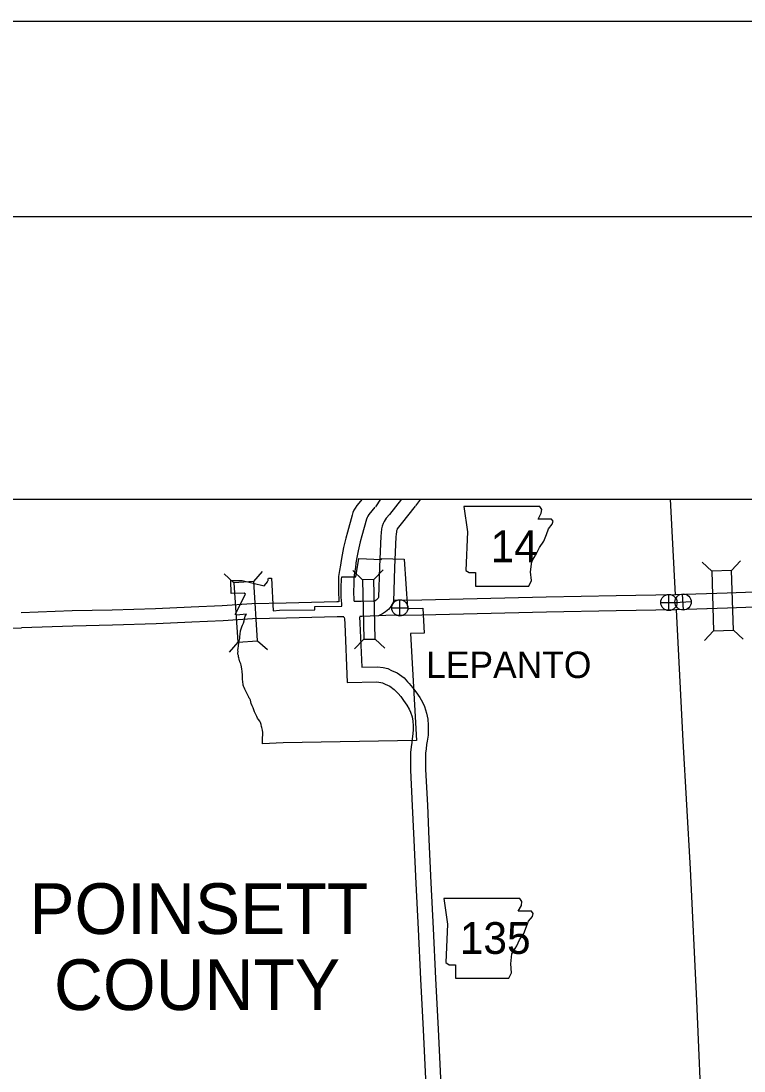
# Model space of a CAD drawing. Extents: x -117616 to 64730, y 54117 to 789866.
# Drawn here: x 61708.6 to 61852.8, y 56041.5 to 56250.9 of the extents above; entities that cross this region are included whole.
import ezdxf

# ---------------------------------------------------------------- set-up
doc = ezdxf.new("R2010")
doc.units = 0
for name, color, linetype in [('10', 7, 'Continuous'), ('2', 7, 'Continuous'), ('20', 7, 'Continuous'), ('26', 7, 'Continuous'), ('Default', 7, 'Continuous'), ('Level 10', 7, 'Continuous'), ('Level 20', 7, 'Continuous'), ('Level 21', 7, 'Continuous'), ('Level 26', 7, 'Continuous'), ('Level 6', 7, 'Continuous'), ('R_Border', 7, 'Continuous'), ('R_No Plot', 7, 'Continuous')]:
    doc.layers.add(name, color=color, linetype=linetype)

msp = doc.modelspace()

# ---------------------------------------------------------------- linework, layer by layer
at = {"layer": '10'}
for points in [[(61894.64, 56138.72), (61871.24, 56137.58), (61849.41, 56136.82), (61839.09, 56136.5)], [(61894.81, 56135.72), (61871.37, 56134.58), (61849.51, 56133.82), (61839.25, 56133.5)], [(61894.81, 56135.72), (61871.37, 56134.58), (61849.51, 56133.82), (61839.35, 56133.5)]]:
    msp.add_lwpolyline(points, dxfattribs=at)
at = {"layer": '2'}
for points in [[(61838.05, 56155.54), (61839.09, 56136.5)], [(61839.25, 56133.5), (61840.62, 56107.34), (61842.03, 56081.82), (61843.35, 56055.55), (61844.48, 56029.1), (61845.71, 56002.55), (61847.12, 55976.46), (61848.14, 55951.87)]]:
    msp.add_lwpolyline(points, dxfattribs=at)
at = {"layer": '20'}
for p, q in [((61846.37, 56141.17), (61844.44, 56142.98)), ((61850.33, 56141.29), (61852.13, 56143.22)), ((61846.74, 56129.29), (61844.94, 56127.37)), ((61850.7, 56129.42), (61852.63, 56127.61))]:
    msp.add_line(p, q, dxfattribs=at)
msp.add_lwpolyline([(61846.37, 56141.17), (61846.74, 56129.29), (61850.7, 56129.42), (61850.33, 56141.29)], close=True, dxfattribs=at)
at = {"layer": '26'}
for p, q in [((61840.75, 56133.41), (61840.55, 56136.66)), ((61839.03, 56134.94), (61842.27, 56135.14))]:
    msp.add_line(p, q, dxfattribs=at)
msp.add_circle((61840.65, 56135.04), 1.62, dxfattribs=at)
at = {"layer": 'Level 10'}
for points in [[(61776.64, 56155.54), (61775.59, 56154.26), (61775.25, 56153.77), (61774.98, 56153.33), (61774.8, 56152.88), (61774.65, 56152.37), (61773.69, 56148.99), (61773.37, 56147.76), (61772.92, 56145.88), (61772.63, 56144.47), (61772.44, 56143.32), (61772.32, 56142.39), (61772.14, 56141.3), (61771.96, 56140.11), (61771.96, 56138.95), (61771.95, 56136.74), (61771.97, 56135.65), (61772, 56135.08)], [(61784.5, 56155.54), (61782.1, 56152.49), (61781.45, 56151.72), (61781.05, 56151.07), (61780.86, 56150.71), (61780.65, 56150.16), (61780.51, 56149.6), (61780.42, 56148.83), (61780.38, 56148.19), (61780.11, 56142.05), (61779.91, 56135.92), (61779.86, 56135.82), (61779.73, 56135.65), (61779.67, 56135.6), (61779.5, 56135.46), (61779.41, 56135.39), (61779.23, 56135.27), (61779.15, 56135.23), (61776.48, 56135.16), (61775.03, 56135.13)], [(61780.29, 56155.54), (61779.28, 56154.03)], [(61788.26, 56155.54), (61787.26, 56154.19)], [(61779.19, 56153.92), (61777.99, 56152.45), (61777.76, 56152.12), (61777.68, 56151.99), (61777.64, 56151.89), (61777.52, 56151.52), (61776.58, 56148.21), (61776.28, 56147.04), (61775.85, 56145.24), (61775.59, 56143.93), (61775.41, 56142.87), (61775.29, 56141.94), (61775.1, 56140.84), (61774.96, 56139.89), (61774.96, 56138.93), (61774.95, 56136.77), (61774.97, 56135.76), (61775, 56135.19)], [(61787.23, 56154.16), (61784.43, 56150.6), (61783.89, 56149.96), (61783.66, 56149.6), (61783.6, 56149.47), (61783.51, 56149.25), (61783.47, 56149.06), (61783.41, 56148.56), (61783.38, 56148.05), (61783.11, 56141.94), (61782.89, 56135.08), (61782.36, 56134.14), (61781.95, 56133.62), (61781.64, 56133.33), (61781.33, 56133.09), (61781.13, 56132.93), (61780.71, 56132.66), (61779.88, 56132.25), (61776.56, 56132.16), (61776.16, 56132.15)], [(61839.12, 56136.48), (61827.28, 56136.28), (61813.36, 56136.01), (61788.52, 56135.42), (61782.97, 56135.37)], [(61771.95, 56135.06), (61771.58, 56135.05), (61761.5, 56134.83), (61754.63, 56134.67), (61748.76, 56134.29), (61742.52, 56134.03), (61735.42, 56133.69), (61726.79, 56133.42), (61718.84, 56133.25), (61708.61, 56132.9)], [(61772.97, 56132.08), (61771.65, 56132.05), (61761.57, 56131.84), (61754.76, 56131.67), (61748.92, 56131.29), (61742.65, 56131.04), (61735.54, 56130.7), (61726.87, 56130.42), (61718.93, 56130.25), (61708.71, 56129.9)], [(61772.99, 56132.04), (61773.06, 56131.94), (61773.14, 56131.65), (61773.2, 56130.67), (61773.68, 56118.97), (61779.58, 56119.09), (61780.34, 56119), (61780.72, 56118.91), (61781.24, 56118.65), (61782.14, 56118.27), (61783.01, 56117.62), (61783.59, 56117.04), (61783.82, 56116.81), (61784.34, 56116.18), (61784.91, 56115.41), (61785.55, 56114.47), (61785.99, 56113.65), (61786.27, 56113.09), (61786.59, 56112.12), (61786.77, 56111.25), (61786.83, 56110.38), (61786.81, 56109.61), (61786.78, 56108.75), (61786.64, 56107.73), (61786.53, 56107.04), (61786.42, 56106.15), (61786.3, 56105.05), (61786.29, 56101.54), (61786.65, 56094.4), (61786.96, 56087.56), (61787.36, 56078.93), (61787.79, 56069.78), (61788.29, 56059.84), (61788.79, 56049.71), (61789.39, 56037.2)], [(61776.12, 56132.08), (61776.2, 56130.83), (61776.56, 56122.03), (61779.73, 56122.09), (61780.86, 56121.96), (61781.74, 56121.75), (61782.48, 56121.38), (61783.64, 56120.9), (61784.99, 56119.89), (61785.72, 56119.15), (61786.05, 56118.82), (61786.7, 56118.02), (61787.35, 56117.15), (61788.12, 56116.03), (61788.65, 56115.04), (61789.05, 56114.23), (61789.49, 56112.89), (61789.74, 56111.65), (61789.83, 56110.46), (61789.81, 56109.53), (61789.78, 56108.49), (61789.61, 56107.3), (61789.51, 56106.63), (61789.4, 56105.79), (61789.29, 56104.87), (61789.29, 56101.62), (61789.65, 56094.55), (61789.95, 56087.7), (61790.36, 56079.07), (61790.79, 56069.92), (61791.29, 56059.99), (61791.78, 56049.86), (61792.39, 56037.32)], [(61839.23, 56133.48), (61827.33, 56133.28), (61813.42, 56133.01), (61788.57, 56132.42), (61781.38, 56132.36), (61779.97, 56132.27)], [(61702.66, 56129.67), (61708.72, 56129.9)]]:
    msp.add_lwpolyline(points, dxfattribs=at)
at = {"layer": 'Level 20'}
for p, q in [((61751.08, 56138.89), (61749.1, 56140.63)), ((61755.04, 56139.14), (61756.78, 56141.13)), ((61776.69, 56139.49), (61774.78, 56141.31)), ((61779, 56139.54), (61780.83, 56141.45)), ((61779, 56139.54), (61776.69, 56139.49)), ((61776.69, 56139.49), (61776.95, 56127.61)), ((61779.27, 56127.66), (61779, 56139.54)), ((61776.95, 56127.61), (61775.13, 56125.7)), ((61776.95, 56127.61), (61779.27, 56127.66)), ((61779.27, 56127.66), (61781.17, 56125.84)), ((61751.85, 56127.03), (61750.1, 56125.05)), ((61755.8, 56127.29), (61757.78, 56125.54))]:
    msp.add_line(p, q, dxfattribs=at)
msp.add_lwpolyline([(61755.8, 56127.29), (61755.04, 56139.14), (61751.08, 56138.89), (61751.85, 56127.03)], close=True, dxfattribs=at)
at = {"layer": 'Level 21'}
for points in [[(61796.89, 56154.1), (61797.65, 56149.03), (61797.31, 56141.33), (61797.99, 56140.91), (61799.25, 56140.91), (61799.25, 56138.2), (61809.91, 56138.2), (61810.42, 56139.3), (61810.25, 56141.08), (61810.51, 56143.11), (61811.44, 56144.71), (61812.03, 56145.9), (61812.87, 56147.17), (61813.38, 56148.52), (61813.8, 56149.62), (61814.57, 56150.55), (61814.73, 56151.14), (61814.4, 56151.57), (61811.77, 56151.57), (61812.37, 56152.75), (61812.45, 56153.51), (61812.1, 56154.1)], [(61792.91, 56075.91), (61793.67, 56070.84), (61793.33, 56063.14), (61794.01, 56062.72), (61795.27, 56062.72), (61795.27, 56060.01), (61805.93, 56060.01), (61806.44, 56061.11), (61806.27, 56062.89), (61806.52, 56064.92), (61807.46, 56066.52), (61808.05, 56067.71), (61808.89, 56068.98), (61809.4, 56070.33), (61809.82, 56071.43), (61810.59, 56072.36), (61810.75, 56072.95), (61810.42, 56073.38), (61807.79, 56073.38), (61808.39, 56074.56), (61808.47, 56075.32), (61808.12, 56075.91)]]:
    msp.add_lwpolyline(points, close=True, dxfattribs=at)
at = {"layer": 'Level 26'}
for p, q in [((61837.81, 56133.31), (61837.81, 56136.56)), ((61782.54, 56133.86), (61785.79, 56133.86)), ((61784.16, 56132.23), (61784.16, 56135.48)), ((61836.19, 56134.94), (61839.44, 56134.94))]:
    msp.add_line(p, q, dxfattribs=at)
for centre in [(61837.81, 56134.94), (61784.16, 56133.86)]:
    msp.add_circle(centre, 1.62, dxfattribs=at)
at = {"layer": 'Level 6'}
for points in [[(61754.72, 56114.32), (61754.52, 56114.82), (61754.43, 56115.15), (61754.36, 56115.45), (61754.31, 56115.61), (61754.23, 56115.72), (61754.14, 56115.85), (61754.03, 56116.07), (61753.88, 56116.35), (61753.68, 56116.73), (61753.5, 56117.15), (61753.23, 56117.67), (61753.09, 56117.96), (61752.98, 56118.24), (61752.92, 56118.46), (61752.92, 56118.74), (61752.88, 56118.97), (61752.85, 56119.23), (61752.8, 56119.55), (61752.76, 56119.77), (61752.75, 56120.03), (61752.75, 56120.35), (61752.77, 56120.66), (61752.74, 56120.98), (61752.7, 56121.25), (61752.67, 56121.63), (61752.6, 56122.08), (61752.52, 56122.42), (61752.42, 56122.72), (61752.28, 56123.12), (61752.26, 56123.17), (61752.2, 56123.34), (61752.13, 56123.67), (61752.03, 56123.92), (61751.98, 56124.13), (61751.97, 56124.37), (61751.88, 56124.65), (61751.84, 56124.83), (61751.89, 56125.16), (61751.88, 56125.44), (61751.93, 56125.8), (61751.97, 56126.28), (61752.06, 56126.9), (61752.13, 56127.23), (61752.21, 56127.51), (61752.24, 56127.79), (61752.23, 56128.07), (61752.3, 56128.6), (61752.41, 56129.26), (61752.51, 56129.72), (61752.63, 56130.1), (61752.77, 56130.39), (61752.96, 56130.85), (61753.11, 56131.28), (61753.21, 56131.63), (61753.33, 56132.19), (61753.56, 56132.61), (61751.59, 56132.4), (61751.55, 56132.57), (61751.3, 56132.56), (61753.38, 56136.62), (61753.11, 56136.83), (61750.55, 56136.74), (61750.46, 56139.3), (61752.7, 56139.35), (61757.07, 56138.26), (61757.5, 56138.75), (61757.74, 56139.04), (61757.8, 56139.14), (61757.84, 56139.24), (61757.87, 56139.34), (61757.89, 56139.49), (61757.91, 56139.61), (61757.98, 56139.77), (61758.59, 56139.8), (61758.92, 56133.29), (61760.19, 56133.38), (61767.23, 56133.46), (61767.19, 56134.15), (61772.59, 56134.24), (61772.57, 56134.66), (61772.47, 56135.99), (61772.45, 56136.98), (61772.48, 56138.08), (61772.53, 56139.54), (61772.56, 56140.03), (61775.37, 56140.08), (61775.97, 56143.69), (61780.47, 56143.51), (61780.47, 56143.72), (61784.99, 56143.59), (61785.69, 56133.75), (61786, 56133.75), (61788.75, 56133.82), (61789.03, 56128.84), (61786.28, 56128.77), (61787.47, 56107.4)], [(61787.47, 56107.4), (61760.86, 56106.94), (61756.79, 56106.77), (61756.77, 56107.08), (61756.77, 56107.37), (61756.78, 56107.68), (61756.79, 56108.02), (61756.82, 56108.47), (61756.82, 56108.68), (61756.81, 56109.02), (61756.77, 56109.46), (61756.72, 56109.72), (61756.62, 56110.02), (61756.59, 56110.24), (61756.52, 56110.6), (61756.47, 56110.82), (61756.38, 56111.02), (61756.22, 56111.27), (61755.97, 56111.64), (61755.78, 56111.89), (61755.62, 56112.18), (61755.49, 56112.46), (61755.35, 56112.76), (61755.2, 56113.14), (61755.06, 56113.57), (61754.91, 56113.96), (61754.72, 56114.32)]]:
    msp.add_lwpolyline(points, dxfattribs=at)
at = {"layer": 'R_Border'}
msp.add_line((61520.24, 56211.92), (64682.04, 56211.92), dxfattribs=at)
at = {"layer": 'R_No Plot'}
msp.add_line((61396.23, 56250.87), (64729.56, 56250.87), dxfattribs=at)
for points in [[(61396.16, 56250.87), (64729.56, 56250.87), (64729.56, 54117.5), (61396.16, 54117.5)], [(61556.57, 56155.54), (62285.97, 56155.54), (62285.97, 55371.05), (61556.57, 55371.05)]]:
    msp.add_lwpolyline(points, close=True, dxfattribs=at)

# ---------------------------------------------------------------- texts
at = {"layer": 'Default'}
for s, p in [('POINSETT', (61710.26, 56068.85)), ('COUNTY', (61715.19, 56053.69))]:
    msp.add_text(s, height=10.107, dxfattribs=at).set_placement(p)
at = {"layer": 'Level 21'}
for s, p in [('14', (61802.26, 56142.96)), ('135', (61796.11, 56064.88))]:
    msp.add_text(s, height=6.336, dxfattribs=at).set_placement(p)
at = {"layer": 'Level 6'}
msp.add_text('LEPANTO', height=5.28, dxfattribs=at).set_placement((61789.41, 56119.88))

doc.saveas('drawing.dxf')
